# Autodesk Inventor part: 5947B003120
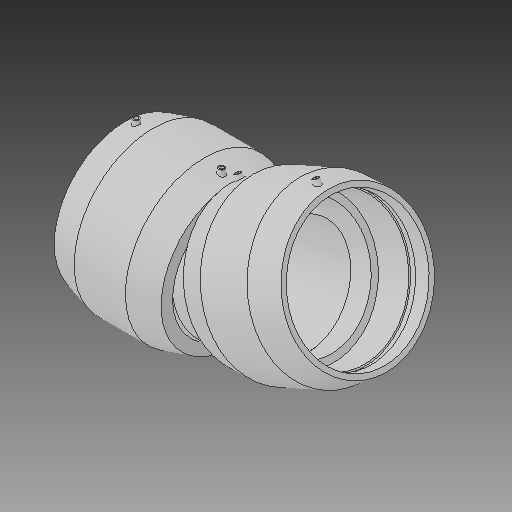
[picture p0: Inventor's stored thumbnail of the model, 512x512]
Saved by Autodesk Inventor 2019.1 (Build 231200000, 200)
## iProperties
Created: 2017-06
Part Number: 5947B003120
Material: Generic
Description: PLASSON ADJUSTABLE ELBOW ASTM 12''
Document SubType Name: Modeling
Designer: KIM
Mass: 16853.5 g
Surface Area: 12350.1 cm^2
Volume: 16853.5 cm^3
Density: 1 g/cm^3
Appearance: Default
Author: KIM
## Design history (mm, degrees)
derived "5947B.ipt"
feature "Solid1::5947B.ipt"
tag "TaggingFeature1"
body "Solid1"
other parameters: "d0" = 261.112, "d2" = 386.08, "d3" = 135.89, "d4" = 67.945, "d5" = 347.472, "d7" = 323.4, "d8" = 168 deg, "d10" = 54.356, "d11" = 18.11867, "d29" = 193.04, "d30" = 15, "d31" = 104.4448, "d34" = 5 deg, "d41" = 4, "d42" = 14, "d43" = 0, "d48" = 291.06, "d49" = 24 deg, "d50" = 652.78, "d51" = 78 deg, "d52" = 90 deg, "d55" = 62.611, "d57" = 168 deg, "d58" = 12.5222, "d60" = 75.81742, "d62" = 3, "d63" = 0, "d_" = 323.4, "L_" = 652.78, "L_1" = 135.89, "D_" = 386.08, "A_" = 193.04, "d54" = 125.222, "d59" = 252.72473
